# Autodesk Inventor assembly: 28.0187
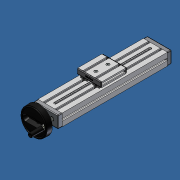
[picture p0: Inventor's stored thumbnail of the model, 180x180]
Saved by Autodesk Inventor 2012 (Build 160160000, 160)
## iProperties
Created: 2007-06
Part Number: 28.0187
Document SubType Name: Assembly
Designer: Andy Moles
Description: ADJUSTING UNIT VEN 45X90S
Author: Andy Moles
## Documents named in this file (15)
- C:\Andys Backup Data\ANDY'S INVENTOR\INVENTOR LIBRARIES\PARTS LIBRARY\READY FOR USE MODULES LG\28.0187 ADJUSTING UNIT VEN 45X90S.iam
- C:\Andys Backup Data\ANDY'S INVENTOR\INVENTOR LIBRARIES\PARTS LIBRARY\READY FOR USE MODULES LG\SUBCOMPONENTS\28.0200 BEARING PLATE 45X90 HANDWHEEL SIDE.ipt
- C:\Andys Backup Data\ANDY'S INVENTOR\INVENTOR LIBRARIES\PARTS LIBRARY\READY FOR USE MODULES LG\SUBCOMPONENTS\50.1264 BALL BEARING 10X30X9 6200 2RS DIN 625.ipt
- C:\Andys Backup Data\ANDY'S INVENTOR\INVENTOR LIBRARIES\PARTS LIBRARY\READY FOR USE MODULES LG\SUBCOMPONENTS\28.0201 BEARING PLATE 45X90 IDLER SIDE.ipt
- C:\Andys Backup Data\ANDY'S INVENTOR\INVENTOR LIBRARIES\PARTS LIBRARY\READY FOR USE MODULES LG\SUBCOMPONENTS\28.0204 HANDWHEEL 100mm.iam
- C:\Andys Backup Data\ANDY'S INVENTOR\INVENTOR LIBRARIES\PARTS LIBRARY\FASTENING ELEMENTS\SCREWS CAP\21.1204 M8X25.ipt
- C:\Andys Backup Data\ANDY'S INVENTOR\INVENTOR LIBRARIES\PARTS LIBRARY\READY FOR USE MODULES LG\SUBCOMPONENTS\28.0215_1.ipt
- C:\Andys Backup Data\ANDY'S INVENTOR\INVENTOR LIBRARIES\PARTS LIBRARY\FASTENING ELEMENTS\WASHERS\21.1326 DISC SPRING 20.ipt
- C:\Andys Backup Data\ANDY'S INVENTOR\INVENTOR LIBRARIES\PARTS LIBRARY\READY FOR USE MODULES LG\SUBCOMPONENTS\28.0221 ACME SCREW 16X4.ipt
- C:\Andys Backup Data\ANDY'S INVENTOR\INVENTOR LIBRARIES\PARTS LIBRARY\READY FOR USE MODULES LG\SUBCOMPONENTS\28.0237_2 LWN-S 90X19-NSC.ipt
- C:\Andys Backup Data\ANDY'S INVENTOR\INVENTOR LIBRARIES\PARTS LIBRARY\COMPONENTS LG\22.1096 SLIDE RAIL LN-S.iam
- C:\Andys Backup Data\ANDY'S INVENTOR\INVENTOR LIBRARIES\PARTS LIBRARY\FASTENING ELEMENTS\SCREWS COUNTERSUNK\21.1543 M5x12 CSUNK.ipt
- C:\Andys Backup Data\ANDY'S INVENTOR\INVENTOR LIBRARIES\PARTS LIBRARY\READY FOR USE MODULES LG\SUBCOMPONENTS\28.0258 Nut slide connector 35.5.ipt
- C:\Andys Backup Data\ANDY'S INVENTOR\INVENTOR LIBRARIES\PARTS LIBRARY\END CAPS\22.1014_1 END CAP 90X19 GRAY.ipt
- C:\Andys Backup Data\ANDY'S INVENTOR\INVENTOR LIBRARIES\PARTS LIBRARY\READY FOR USE MODULES LG\SUBCOMPONENTS\28.0257 BRONZE NUT 16X4 NOTCHED.ipt
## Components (22 placed, 14 different names)
1. 28.0215_1:1 — Flush:1, Mate:13, Flush:2, Mate:15, Flush:3, Angle:2, Flush:4, Mate:18, Flush:5, Flush:6, Angle:8, Mate:26, Mate:28
2. 28.0200 BEARING PLATE 45X90 HANDWHEEL SIDE:1 — Insert:4, Insert:6, Insert:7, Insert:11, Mate:15, Flush:3, Flush:4
3. 50.1264 10X30X9 6200 2RS DIN 625 BALL BEARING:1 — Insert:11, Insert:14
4. 50.1264 10X30X9 6200 2RS DIN 625 BALL BEARING:2 — Insert:10
5. 28.0201 BEARING PLATE 45X90 IDLER SIDE:1 — Insert:8, Insert:9, Insert:10, Angle:2, Mate:18, Flush:5, Flush:6
6. 28.0204 HANDWHEEL 100mm:1 [sub-assembly] — Insert:4
7. 21.1204  M8 x 25:1 — Insert:6
8. 21.1204  M8 x 25:2 — Insert:7
9. 21.1204  M8 x 25:3 — Insert:8
10. 21.1204  M8 x 25:4 — Insert:9
11. 21.1326 DISC SPRING 20:1
12. 21.1326 DISC SPRING 20:2 — Insert:13, Insert:14
13. 28.0221 ACME SCREW 16X4:1 — Insert:13, Mate:27
14. 28.0237_2 LWN-S 90X19-NSC:1 — Mate:19, Mate:20, Mate:21, Mate:22, Angle:4, Angle:5, Insert:15, Insert:16, Insert:17, Angle:6, Flush:7, Flush:8, Mate:23, Mate:24, Flush:9, Flush:10, Angle:8, Mate:28
15. 22.1096 SLIDE RAIL LN-S:1 [sub-assembly] — Mate:19, Mate:22, Angle:4
16. 22.1096 SLIDE RAIL LN-S:2 [sub-assembly] — Mate:20, Mate:21, Angle:5, Mate:26
17. 21.1543 M5x12 C'SUNK:1 — Insert:15
18. 21.1543 M5x12 C'SUNK:2 — Insert:16
19. 28.0258 Nut slide connector 35.5:1 — Insert:17, Angle:6, Mate:25, Angle:7
20. 22.1014_1 END CAP 90X19 GRAY:1 — Mate:24, Flush:9, Flush:10
21. 22.1014_1 END CAP 90X19 GRAY:2 — Flush:7, Flush:8, Mate:23
22. 28.0257 BRONZE NUT 16X4 NOTCHED:1 — Mate:25, Angle:7, Mate:27
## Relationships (41: Mate 13, Insert 12, Flush 10, Angle 6)
- Insert:4: 28.0200 BEARING PLATE 45X90 HANDWHEEL SIDE:1 ↔ 28.0204 HANDWHEEL 100mm:1
- Insert:6: 28.0200 BEARING PLATE 45X90 HANDWHEEL SIDE:1 ↔ 21.1204  M8 x 25:1
- Insert:7: 28.0200 BEARING PLATE 45X90 HANDWHEEL SIDE:1 ↔ 21.1204  M8 x 25:2
- Insert:8: 28.0201 BEARING PLATE 45X90 IDLER SIDE:1 ↔ 21.1204  M8 x 25:3
- Insert:9: 28.0201 BEARING PLATE 45X90 IDLER SIDE:1 ↔ 21.1204  M8 x 25:4
- Insert:10: 50.1264 10X30X9 6200 2RS DIN 625 BALL BEARING:2 ↔ 28.0201 BEARING PLATE 45X90 IDLER SIDE:1
- Insert:11: 28.0200 BEARING PLATE 45X90 HANDWHEEL SIDE:1 ↔ 50.1264 10X30X9 6200 2RS DIN 625 BALL BEARING:1
- Flush:1: 28.0215_1:1
- Mate:13: 28.0215_1:1
- Flush:2: 28.0215_1:1
- Mate:15: 28.0215_1:1 ↔ 28.0200 BEARING PLATE 45X90 HANDWHEEL SIDE:1
- Flush:3: 28.0215_1:1 ↔ 28.0200 BEARING PLATE 45X90 HANDWHEEL SIDE:1
- Angle:2: 28.0215_1:1 ↔ 28.0201 BEARING PLATE 45X90 IDLER SIDE:1
- Flush:4: 28.0215_1:1 ↔ 28.0200 BEARING PLATE 45X90 HANDWHEEL SIDE:1
- Mate:18: 28.0215_1:1 ↔ 28.0201 BEARING PLATE 45X90 IDLER SIDE:1
- Flush:5: 28.0215_1:1 ↔ 28.0201 BEARING PLATE 45X90 IDLER SIDE:1
- Flush:6: 28.0215_1:1 ↔ 28.0201 BEARING PLATE 45X90 IDLER SIDE:1
- Insert:13: 21.1326 DISC SPRING 20:2 ↔ 28.0221 ACME SCREW 16X4:1
- Insert:14: 50.1264 10X30X9 6200 2RS DIN 625 BALL BEARING:1 ↔ 21.1326 DISC SPRING 20:2
- Mate:19: 28.0237_2 LWN-S 90X19-NSC:1 ↔ 22.1096 SLIDE RAIL LN-S:1
- Mate:20: 28.0237_2 LWN-S 90X19-NSC:1 ↔ 22.1096 SLIDE RAIL LN-S:2
- Mate:21: 28.0237_2 LWN-S 90X19-NSC:1 ↔ 22.1096 SLIDE RAIL LN-S:2
- Mate:22: 28.0237_2 LWN-S 90X19-NSC:1 ↔ 22.1096 SLIDE RAIL LN-S:1
- Angle:4: 28.0237_2 LWN-S 90X19-NSC:1 ↔ 22.1096 SLIDE RAIL LN-S:1
- Angle:5: 28.0237_2 LWN-S 90X19-NSC:1 ↔ 22.1096 SLIDE RAIL LN-S:2
- Insert:15: 28.0237_2 LWN-S 90X19-NSC:1 ↔ 21.1543 M5x12 C'SUNK:1
- Insert:16: 28.0237_2 LWN-S 90X19-NSC:1 ↔ 21.1543 M5x12 C'SUNK:2
- Insert:17: 28.0237_2 LWN-S 90X19-NSC:1 ↔ 28.0258 Nut slide connector 35.5:1
- Angle:6: 28.0237_2 LWN-S 90X19-NSC:1 ↔ 28.0258 Nut slide connector 35.5:1
- Flush:7: 28.0237_2 LWN-S 90X19-NSC:1 ↔ 22.1014_1 END CAP 90X19 GRAY:2
- Flush:8: 28.0237_2 LWN-S 90X19-NSC:1 ↔ 22.1014_1 END CAP 90X19 GRAY:2
- Mate:23: 28.0237_2 LWN-S 90X19-NSC:1 ↔ 22.1014_1 END CAP 90X19 GRAY:2
- Mate:24: 28.0237_2 LWN-S 90X19-NSC:1 ↔ 22.1014_1 END CAP 90X19 GRAY:1
- Flush:9: 28.0237_2 LWN-S 90X19-NSC:1 ↔ 22.1014_1 END CAP 90X19 GRAY:1
- Flush:10: 28.0237_2 LWN-S 90X19-NSC:1 ↔ 22.1014_1 END CAP 90X19 GRAY:1
- Mate:25: 28.0258 Nut slide connector 35.5:1 ↔ 28.0257 BRONZE NUT 16X4 NOTCHED:1
- Angle:7: 28.0258 Nut slide connector 35.5:1 ↔ 28.0257 BRONZE NUT 16X4 NOTCHED:1
- Angle:8: 28.0215_1:1 ↔ 28.0237_2 LWN-S 90X19-NSC:1
- Mate:26: 28.0215_1:1 ↔ 22.1096 SLIDE RAIL LN-S:2
- Mate:27: 28.0221 ACME SCREW 16X4:1 ↔ 28.0257 BRONZE NUT 16X4 NOTCHED:1
- Mate:28: 28.0215_1:1 ↔ 28.0237_2 LWN-S 90X19-NSC:1
